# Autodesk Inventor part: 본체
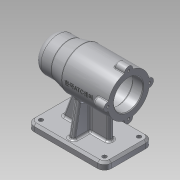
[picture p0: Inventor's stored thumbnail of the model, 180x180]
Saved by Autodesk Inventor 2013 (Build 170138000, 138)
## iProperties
Created: 2019-07
Part Number: 본체
Material: 알루미늄 6061
Document SubType Name: Modeling
Designer: Administrator
Density: 2.71 g/cm^3
Mass: 646.774 g
Surface Area: 654.083 cm^2
Volume: 238.662 cm^3
Author: Administrator
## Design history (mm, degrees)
sketch "스케치1"
  geometry: L1 (-45, 0)-(67, 0); L2 (-45, 0)-(-45, 25); L3 (-45, 25)-(-20, 25); L4 (-20, 25)-(0, 30); L5 (0, 30)-(67, 30); L6 (67, 30)-(67, 21); L7 (67, 21)-(52, 21); L8 (52, 21)-(52, 24); L9 (52, 24)-(-2, 24); L10 (-2, 24)-(-2, 21); L11 (-2, 21)-(-14, 21); L12 (-14, 21)-(-14, 17.5); L13 (-14, 17.5)-(-32, 17.5); L14 (-32, 17.5)-(-32, 16); L15 (-32, 16)-(-36, 16); L16 (-36, 16)-(-36, 10.5); L17 (-36, 10.5)-(-39, 10.5); L18 (-39, 10.5)-(-39, 0); 2 further points
  constraints: 36 end point, 8 horizontal, 8 vertical, 2 point on line, 1 collinear, 1 midpoint, 1 vertical alignment
  dimensions: "d0" = 112 distance of L1.start L1.end; "d2" = 45 distance of L1.start point (0, 0); "d3" = 48 diameter of L9 L1; "d4" = 42 diameter of L7 L1; "d5" = 60 diameter of L5 L1; "d6" = 25 distance of L2.end L3.end; "d7" = 45 distance from line of L4.end L2; "d8" = 50 diameter of L3 L1; "d10" = 42 diameter of L11 L1; "d11" = 35 diameter of L13 L1; "d12" = 32 diameter of L15 L1; "d13" = 21 diameter of L17 L1; "d14" = 54 distance between parallel lines of L10 L8; "d15" = 15 distance of L6.end L7.end; "d16" = 12 distance of L10.end L11.end; "d17" = 18 distance of L12.end L13.end; "d18" = 4 distance of L14.end L15.end; "d19" = 3 distance of L16.end L17.end
revolve "회전1" sketch "스케치1" stored, may be unused: angle "d20" = 90 deg
sketch "스케치2"
  geometry: C1 r 21 at (0, 0) reference; C2 r 6 at (0, 30); 1 further point
  constraints: 2 vertical alignment, 1 centre point, 1 other
  dimensions: "d21" = 12 diameter of C2
extrude "돌출1" join sketch "스케치2" distance "d23" = 16; taper "d24" = 0 deg
sketch "스케치3"
  geometry: A1 r 6 centre (0, 0) between (5.97, -0.6) and (-5.97, -0.6) reference; 1 further point
  constraints: 1 coincident
hole "구멍1" sketch "스케치3" at (0, 0) diameter "d25" = 3.242; stored, may be unused: countersink angle "d29" = 90 deg, drill point angle "d31" = 118 deg; dims "d26" = 8, "d27" = 4, "d28" = 2, "d30" = 11
node "작업 평면1"
sketch "스케치4"
  geometry: L1 (-67, -5.97)-(-67, -29.4) reference; L2 (-67, -35)-(45, -35); L3 (45, -35)-(45, 35); L4 (45, 35)-(-67, 35); L5 (-67, 35)-(-67, -35); 2 further points
  constraints: 8 end point, 2 parallel, 1 collinear, 1 horizontal, 1 horizontal alignment, 1 midpoint, 1 perpendicular
  dimensions: "d36" = 112 distance of L2.start L2.end; "d38" = 70 distance of L4.end L2.start
extrude "돌출2" join sketch "스케치4" distance "d39" = 10; taper "d40" = 0 deg
sketch "스케치5"
  geometry: L1 (67, 35)-(11, 35); L2 (11, 35)-(11, 0); L3 (7, -4)-(15, -4); L4 (15, -4)-(15, 4); L5 (15, 4)-(7, 4); L6 (7, 4)-(7, -4); L7 (7, -4)-(15, 4); L8 (15, -4)-(7, 4); 2 further points
  constraints: 16 end point, 3 midpoint, 2 horizontal, 2 parallel, 1 horizontal alignment, 1 perpendicular, 1 vertical
  dimensions: "d41" = 56 distance of L1.start L1.end; "d42" = 8 distance of L3.end L4.end; "d43" = 8 distance of L3.start L3.end
extrude "돌출3" join sketch "스케치5" stored distance "d44" = 10; taper "d45" = 0 deg
node "작업 평면2"
sketch "스케치6"
  geometry: L1 (39, 0)-(-31, 0) reference; L2 (39, -10)-(39, 0) reference; L3 (-31, -10)-(-31, 0) reference; L4 (32, 0)-(27.265, 26.851); L5 (-24, 0)-(-19.735, 24.186); 1 further point
  constraints: 4 end point, 2 point on line
  dimensions: "d46" = 7 distance from line of L2 L4.start; "d47" = 7 distance of L1.end L5.start; "d48" = 100 deg angle of L1 L5; "d49" = 100 deg angle of L1 L4
feature "리브1" dims "d50" = 1, "d51" = 8, "d52" = 0, "d53" = 0, "d54" = 1, "d55" = 1
feature "리브2" dims "d56" = 1, "d57" = 8, "d58" = 0, "d59" = 0, "d60" = 1, "d61" = 1
sketch "스케치7"
  geometry: L1 (67, -70)-(-45, -70) reference; L2 (-45, -80)-(-45, -70) reference; L3 (-25, -70)-(-13.875, -39.433); L4 (42, -70)-(42, -33.942); L5 (67, -80)-(67, -70) reference; 1 further point
  constraints: 4 end point, 2 point on line, 1 vertical
  dimensions: "d62" = 110 deg angle of L1 L3; "d63" = 20 distance from line of L2 L3.start; "d64" = 25 distance from line of L5 L4.start
feature "리브3" dims "d65" = 1, "d66" = 8, "d67" = 0, "d68" = 0, "d69" = 1, "d70" = 1
feature "리브4" dims "d71" = 1, "d72" = 8, "d73" = 0, "d74" = 0, "d75" = 1, "d76" = 1
fillet "모깎기1" dims "d77" = 10
chamfer "모따기1" distance "d78" = 3; stored, may be unused: second distance "d79" = 2, angle "d80" = 45 deg
sketch "스케치8"
  geometry: A1 r 7 centre (57, 25) between (64, 25) and (57, 32) reference; A2 r 7 centre (-35, 25) between (-35, 32) and (-42, 25) reference; A3 r 7 centre (-35, -25) between (-42, -25) and (-35, -32) reference; A4 r 7 centre (57, -25) between (57, -32) and (64, -25) reference; 5 further points
  constraints: 4 coincident
hole "구멍2" sketch "스케치8" at (-35, 25), (57, 25), (57, -25), (-35, -25) diameter "d81" = 6; stored, may be unused: countersink angle "d85" = 90 deg, drill point angle "d87" = 118 deg; dims "d82" = 8, "d83" = 4, "d84" = 2, "d86" = 11
fillet "모깎기2" dims "d88" = 3
fillet "모깎기3" dims "d98" = 1
fillet "모깎기4" dims "d90" = 3
fillet "모깎기5" dims "d91" = 3
fillet "모깎기6" dims "d92" = 3, "d93" = 0.3
node "작업 평면3"
sketch "스케치9"
  geometry: L1 (67, 6.771)-(67, 29.226) reference; 2 further points
  constraints: 1 horizontal alignment, 1 other
  dimensions: "d95" = 42 distance from line of L1 point (25, 0)
feature "엠보싱1" sketch "스케치9" dims "d96" = 0.5, "d97" = 0
chamfer "모따기2" distance "d99" = 1; stored, may be unused: second distance "d100" = 2, angle "d101" = 45 deg
node "솔리드1"
pattern_circular "원형 패턴1" dims angle "d33" = 360 deg
other parameters: "d94" = 31
